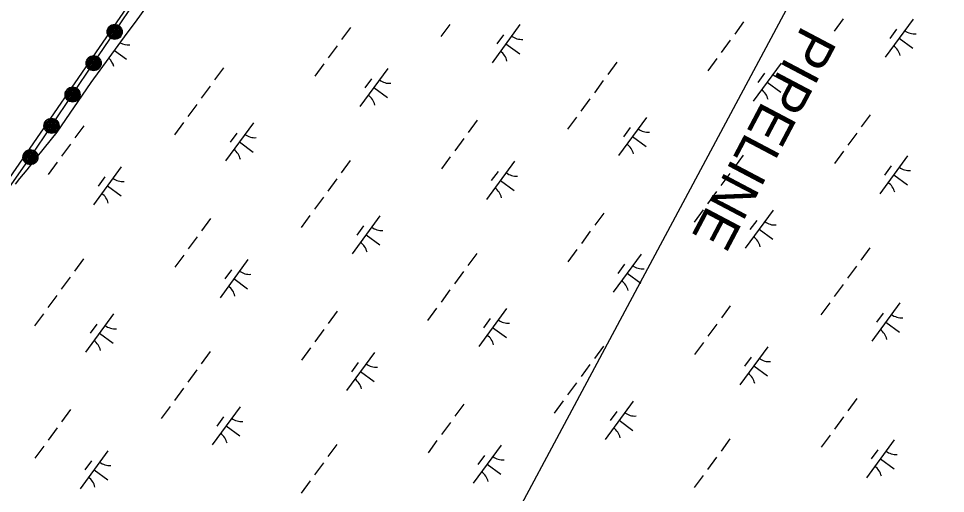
# Model space of a CAD drawing. Extents: x 3905714 to 3926767, y 183354 to 205755.
# Drawn here: x 3917054 to 3918037, y 190967 to 191470 of the extents above; entities that cross this region are included whole.
import ezdxf

# ---------------------------------------------------------------- set-up
doc = ezdxf.new("R2010")
doc.units = 0
for name, color, linetype in [('V-RIVR-EDGE', 7, 'Continuous'), ('V-RRAP-FSHR', 7, 'Continuous'), ('V-TOPO-SHOR', 7, 'Continuous'), ('V-UTIL-IDEN', 7, 'Continuous'), ('V-UTIL-LINE', 7, 'Continuous'), ('V-WETL-SWMP', 7, 'Continuous')]:
    doc.layers.add(name, color=color, linetype=linetype)

msp = doc.modelspace()

# ---------------------------------------------------------------- linework, layer by layer
at = {"layer": 'V-RIVR-EDGE'}
msp.add_lwpolyline([(3917620.57, 192168.81), (3917187.32, 191508.71), (3917014.39, 191257.68)], dxfattribs=at)
at = {"layer": 'V-RRAP-FSHR'}
for points in [[(3917043.93, 191290.26), (3917066.94, 191322.99), (3917089.31, 191356.14), (3917111.62, 191389.34), (3917133.93, 191422.55), (3917156.23, 191455.75), (3917178.54, 191488.95), (3917200.82, 191522.17), (3917223.43, 191555.43), (3917245.27, 191588.69), (3917267.49, 191621.95), (3917289.71, 191655.21), (3917311.94, 191688.47), (3917334.16, 191721.72), (3917356.37, 191754.99), (3917378.57, 191788.26), (3917400.78, 191821.54), (3917422.98, 191854.8), (3917444.62, 191888.45), (3917466.21, 191922.12), (3917487.8, 191955.79), (3917509.39, 191989.46)], [(3917154.18, 191448.72), (3917152.39, 191449.79), (3917150.04, 191452.07), (3917149.13, 191454.48), (3917149.34, 191457.68), (3917150.71, 191460.08), (3917153.18, 191462.3), (3917156.07, 191462.61), (3917158.34, 191462.63), (3917160.78, 191461.17), (3917162.4, 191459.24), (3917163.16, 191457), (3917163.26, 191454.79), (3917162.44, 191452.3), (3917160.02, 191449.81), (3917157.03, 191448.71), (3917154.62, 191448.81), (3917152.24, 191451.4), (3917150.45, 191453.77), (3917150.38, 191456.56), (3917151.59, 191459.56), (3917154.13, 191461.34), (3917157.13, 191461.62), (3917159.75, 191460.63), (3917161.71, 191458.26), (3917162.2, 191455.32), (3917160.93, 191452.12), (3917158.4, 191450.29), (3917155.66, 191449.77), (3917152.82, 191451.58), (3917151.54, 191454.02), (3917151.4, 191456.86), (3917152.71, 191459.29), (3917155.01, 191460.61), (3917157.77, 191460.62), (3917160.22, 191458.66), (3917161.17, 191455.98), (3917159.81, 191452.34), (3917157.38, 191450.87), (3917155.48, 191450.92), (3917153.27, 191453.04), (3917152.21, 191455.72), (3917152.94, 191458.05), (3917155.42, 191459.8), (3917157.76, 191459.46), (3917160, 191457.33), (3917159.96, 191454.92), (3917158.73, 191452.82), (3917156.88, 191451.7), (3917154.9, 191452.26), (3917153.85, 191453.95), (3917153.22, 191456.17), (3917154.28, 191457.96), (3917156.06, 191458.77), (3917158.14, 191458.08), (3917159.06, 191456.41), (3917158.9, 191454.65), (3917157.41, 191453), (3917156.08, 191452.87), (3917154.77, 191454.39), (3917154.34, 191456.26), (3917155.12, 191457.47), (3917156.68, 191457.58), (3917158.18, 191456.47), (3917157.97, 191454.85), (3917156.96, 191453.97), (3917155.54, 191454.79), (3917155.37, 191456.42), (3917156.52, 191456.67), (3917157.15, 191455.72), (3917156.86, 191454.92), (3917156.2, 191455.72)], [(3917131.87, 191415.52), (3917130.08, 191416.58), (3917127.74, 191418.86), (3917126.82, 191421.28), (3917127.03, 191424.48), (3917128.4, 191426.88), (3917130.87, 191429.09), (3917133.76, 191429.41), (3917136.04, 191429.43), (3917138.47, 191427.97), (3917140.1, 191426.03), (3917140.85, 191423.8), (3917140.95, 191421.58), (3917140.13, 191419.1), (3917137.71, 191416.6), (3917134.72, 191415.51), (3917132.32, 191415.61), (3917129.93, 191418.2), (3917128.14, 191420.57), (3917128.08, 191423.36), (3917129.28, 191426.36), (3917131.82, 191428.14), (3917134.82, 191428.41), (3917137.44, 191427.43), (3917139.4, 191425.05), (3917139.9, 191422.11), (3917138.63, 191418.91), (3917136.1, 191417.09), (3917133.35, 191416.57), (3917130.51, 191418.37), (3917129.23, 191420.82), (3917129.09, 191423.66), (3917130.41, 191426.09), (3917132.7, 191427.41), (3917135.46, 191427.42), (3917137.91, 191425.46), (3917138.86, 191422.77), (3917137.51, 191419.14), (3917135.08, 191417.67), (3917133.17, 191417.71), (3917130.96, 191419.83), (3917129.91, 191422.52), (3917130.63, 191424.85), (3917133.11, 191426.6), (3917135.46, 191426.26), (3917137.69, 191424.13), (3917137.66, 191421.72), (3917136.42, 191419.62), (3917134.58, 191418.5), (3917132.59, 191419.06), (3917131.54, 191420.75), (3917130.92, 191422.97), (3917131.98, 191424.76), (3917133.76, 191425.57), (3917135.83, 191424.88), (3917136.75, 191423.2), (3917136.59, 191421.44), (3917135.1, 191419.8), (3917133.78, 191419.67), (3917132.47, 191421.18), (3917132.04, 191423.06), (3917132.81, 191424.27), (3917134.37, 191424.38), (3917135.88, 191423.26), (3917135.67, 191421.64), (3917134.66, 191420.77), (3917133.23, 191421.59), (3917133.06, 191423.22), (3917134.21, 191423.46), (3917134.84, 191422.51), (3917134.56, 191421.72), (3917133.89, 191422.52)], [(3917109.56, 191382.32), (3917107.77, 191383.38), (3917105.43, 191385.66), (3917104.51, 191388.07), (3917104.73, 191391.28), (3917106.09, 191393.68), (3917108.57, 191395.89), (3917111.46, 191396.2), (3917113.73, 191396.23), (3917116.17, 191394.77), (3917117.79, 191392.83), (3917118.54, 191390.6), (3917118.64, 191388.38), (3917117.82, 191385.9), (3917115.4, 191383.4), (3917112.41, 191382.31), (3917110.01, 191382.41), (3917107.63, 191384.99), (3917105.83, 191387.36), (3917105.77, 191390.15), (3917106.97, 191393.15), (3917109.51, 191394.94), (3917112.52, 191395.21), (3917115.13, 191394.23), (3917117.1, 191391.85), (3917117.59, 191388.91), (3917116.32, 191385.71), (3917113.79, 191383.89), (3917111.04, 191383.37), (3917108.2, 191385.17), (3917106.92, 191387.62), (3917106.79, 191390.46), (3917108.1, 191392.89), (3917110.39, 191394.2), (3917113.15, 191394.22), (3917115.6, 191392.25), (3917116.55, 191389.57), (3917115.2, 191385.93), (3917112.77, 191384.47), (3917110.86, 191384.51), (3917108.66, 191386.63), (3917107.6, 191389.31), (3917108.32, 191391.65), (3917110.81, 191393.4), (3917113.15, 191393.06), (3917115.38, 191390.92), (3917115.35, 191388.51), (3917114.12, 191386.42), (3917112.27, 191385.3), (3917110.28, 191385.85), (3917109.23, 191387.55), (3917108.61, 191389.76), (3917109.67, 191391.55), (3917111.45, 191392.37), (3917113.52, 191391.68), (3917114.44, 191390), (3917114.28, 191388.24), (3917112.79, 191386.6), (3917111.47, 191386.47), (3917110.16, 191387.98), (3917109.73, 191389.86), (3917110.5, 191391.06), (3917112.06, 191391.18), (3917113.57, 191390.06), (3917113.36, 191388.44), (3917112.35, 191387.57), (3917110.93, 191388.38), (3917110.75, 191390.02), (3917111.91, 191390.26), (3917112.54, 191389.31), (3917112.25, 191388.52), (3917111.59, 191389.31)], [(3917087.26, 191349.12), (3917085.47, 191350.18), (3917083.12, 191352.46), (3917082.21, 191354.87), (3917082.42, 191358.08), (3917083.79, 191360.47), (3917086.26, 191362.69), (3917089.15, 191363), (3917091.42, 191363.03), (3917093.86, 191361.57), (3917095.48, 191359.63), (3917096.24, 191357.39), (3917096.34, 191355.18), (3917095.52, 191352.7), (3917093.1, 191350.2), (3917090.11, 191349.11), (3917087.7, 191349.2), (3917085.32, 191351.79), (3917083.53, 191354.16), (3917083.46, 191356.95), (3917084.67, 191359.95), (3917087.21, 191361.74), (3917090.21, 191362.01), (3917092.83, 191361.02), (3917094.79, 191358.65), (3917095.28, 191355.71), (3917094.01, 191352.51), (3917091.48, 191350.68), (3917088.74, 191350.17), (3917085.9, 191351.97), (3917084.62, 191354.42), (3917084.48, 191357.26), (3917085.79, 191359.69), (3917088.09, 191361), (3917090.85, 191361.02), (3917093.3, 191359.05), (3917094.25, 191356.37), (3917092.89, 191352.73), (3917090.46, 191351.26), (3917088.56, 191351.31), (3917086.35, 191353.43), (3917085.29, 191356.11), (3917086.02, 191358.44), (3917088.5, 191360.2), (3917090.84, 191359.86), (3917093.07, 191357.72), (3917093.04, 191355.31), (3917091.81, 191353.21), (3917089.96, 191352.09), (3917087.98, 191352.65), (3917086.93, 191354.34), (3917086.3, 191356.56), (3917087.36, 191358.35), (3917089.14, 191359.16), (3917091.22, 191358.47), (3917092.14, 191356.8), (3917091.98, 191355.04), (3917090.49, 191353.4), (3917089.16, 191353.26), (3917087.85, 191354.78), (3917087.42, 191356.65), (3917088.2, 191357.86), (3917089.76, 191357.98), (3917091.26, 191356.86), (3917091.05, 191355.24), (3917090.04, 191354.36), (3917088.62, 191355.18), (3917088.45, 191356.81), (3917089.6, 191357.06), (3917090.23, 191356.11), (3917089.94, 191355.31), (3917089.28, 191356.11)], [(3917064.73, 191316.01), (3917062.97, 191317.1), (3917060.67, 191319.43), (3917059.81, 191321.87), (3917060.09, 191325.07), (3917061.5, 191327.43), (3917064.02, 191329.6), (3917066.92, 191329.85), (3917069.19, 191329.82), (3917071.6, 191328.31), (3917073.18, 191326.34), (3917073.89, 191324.09), (3917073.94, 191321.87), (3917073.07, 191319.41), (3917070.59, 191316.96), (3917067.58, 191315.93), (3917065.18, 191316.08), (3917062.85, 191318.72), (3917061.11, 191321.13), (3917061.11, 191323.92), (3917062.37, 191326.89), (3917064.95, 191328.62), (3917067.96, 191328.83), (3917070.56, 191327.79), (3917072.47, 191325.38), (3917072.9, 191322.43), (3917071.56, 191319.25), (3917068.99, 191317.48), (3917066.24, 191317.02), (3917063.43, 191318.89), (3917062.21, 191321.36), (3917062.13, 191324.2), (3917063.5, 191326.6), (3917065.82, 191327.87), (3917068.58, 191327.83), (3917070.98, 191325.81), (3917071.88, 191323.11), (3917070.45, 191319.5), (3917067.98, 191318.08), (3917066.08, 191318.17), (3917063.92, 191320.34), (3917062.92, 191323.04), (3917063.69, 191325.36), (3917066.21, 191327.06), (3917068.55, 191326.67), (3917070.73, 191324.49), (3917070.65, 191322.08), (3917069.37, 191320.01), (3917067.5, 191318.92), (3917065.53, 191319.52), (3917064.52, 191321.24), (3917063.94, 191323.47), (3917065.04, 191325.24), (3917066.83, 191326.01), (3917068.89, 191325.28), (3917069.78, 191323.58), (3917069.58, 191321.83), (3917068.05, 191320.22), (3917066.73, 191320.11), (3917065.45, 191321.65), (3917065.06, 191323.54), (3917065.86, 191324.73), (3917067.42, 191324.81), (3917068.9, 191323.66), (3917068.66, 191322.05), (3917067.63, 191321.19), (3917066.22, 191322.04), (3917066.08, 191323.68), (3917067.24, 191323.9), (3917067.85, 191322.93), (3917067.55, 191322.14), (3917066.9, 191322.96)]]:
    msp.add_lwpolyline(points, dxfattribs=at)
for centre in [(3917156.23, 191455.75), (3917133.93, 191422.55), (3917111.62, 191389.35), (3917089.31, 191356.14), (3917066.94, 191322.99)]:
    msp.add_circle(centre, 8, dxfattribs=at)
at = {"layer": 'V-TOPO-SHOR'}
msp.add_lwpolyline([(3917051.15, 191294.52), (3917055.86, 191300.49), (3917063.34, 191309.67), (3917074.55, 191323.7), (3917095.19, 191349.54), (3917131.19, 191402.2), (3917169.41, 191454.44), (3917178.42, 191465.97), (3917191.16, 191483.89), (3917199.6, 191498.2), (3917229.36, 191546.82), (3917293.04, 191649.06), (3917339.54, 191727.55), (3917392.7, 191814.09), (3917467.19, 191926.89), (3917531.43, 192020.67)], dxfattribs=at)
at = {"layer": 'V-UTIL-LINE'}
msp.add_lwpolyline([(3922094.67, 198742.56), (3921080.02, 197477.61), (3915734.79, 187496.67)], dxfattribs=at)
at = {"layer": 'V-WETL-SWMP'}
for p, q in [((3917178.42, 191465.97), (3917191.16, 191483.89)), ((3917928.15, 191469.6), (3917918.7, 191456.69)), ((3917169.41, 191454.44), (3917178.42, 191465.97)), ((3917406.07, 191460.48), (3917396.61, 191447.58)), ((3917511.48, 191463.78), (3917502.02, 191450.87)), ((3917585.66, 191463.45), (3917556.11, 191423.11)), ((3917822.74, 191466.31), (3917813.29, 191453.4)), ((3918002.34, 191469.27), (3917972.79, 191428.94)), ((3917131.19, 191402.2), (3917169.41, 191454.44)), ((3917568.21, 191452.68), (3917561.12, 191443)), ((3917984.88, 191458.51), (3917977.79, 191448.83)), ((3917391.88, 191441.12), (3917382.43, 191428.22)), ((3917570.89, 191443.28), (3917585.41, 191432.64)), ((3917808.56, 191446.95), (3917799.1, 191434.04)), ((3917987.56, 191449.11), (3918002.08, 191438.47)), ((3917156.02, 191436.13), (3917168.74, 191426.82)), ((3917377.7, 191421.76), (3917368.24, 191408.86)), ((3917688.21, 191423.55), (3917678.76, 191410.64)), ((3917794.37, 191427.59), (3917784.92, 191414.68)), ((3917862.38, 191422.76), (3917832.83, 191382.42)), ((3917271.54, 191417.73), (3917262.08, 191404.82)), ((3917445.71, 191416.93), (3917416.16, 191376.6)), ((3917844.93, 191411.99), (3917837.84, 191402.31)), ((3917095.19, 191349.54), (3917131.19, 191402.2)), ((3917428.26, 191406.17), (3917421.16, 191396.49)), ((3917674.03, 191404.19), (3917664.57, 191391.28)), ((3917847.61, 191402.59), (3917862.13, 191391.95)), ((3917257.35, 191398.37), (3917247.9, 191385.46)), ((3917430.93, 191396.77), (3917445.45, 191386.13)), ((3917659.84, 191384.83), (3917650.39, 191371.92)), ((3917243.17, 191379.01), (3917233.71, 191366.1)), ((3917540.25, 191362.18), (3917530.79, 191349.27)), ((3917645.66, 191365.47), (3917636.2, 191352.56)), ((3917719.84, 191365.14), (3917690.29, 191324.81)), ((3917956.92, 191368), (3917947.46, 191355.1)), ((3917123.57, 191356.35), (3917114.12, 191343.45)), ((3917228.99, 191359.65), (3917219.53, 191346.74)), ((3917303.17, 191359.32), (3917273.62, 191318.98)), ((3917702.39, 191354.38), (3917695.3, 191344.7)), ((3917074.56, 191323.7), (3917095.19, 191349.54)), ((3917285.72, 191348.55), (3917278.62, 191338.87)), ((3917526.06, 191342.82), (3917516.61, 191329.91)), ((3917705.07, 191344.98), (3917719.59, 191334.34)), ((3917942.74, 191348.64), (3917933.28, 191335.74)), ((3917109.39, 191336.99), (3917099.93, 191324.09)), ((3917288.39, 191339.15), (3917302.91, 191328.51)), ((3917063.34, 191309.67), (3917074.56, 191323.7)), ((3917511.88, 191323.46), (3917502.42, 191310.55)), ((3917822.39, 191325.24), (3917812.93, 191312.34)), ((3917928.55, 191329.28), (3917919.1, 191316.38)), ((3917996.56, 191324.45), (3917967.01, 191284.12)), ((3917095.21, 191317.63), (3917085.75, 191304.73)), ((3917163.21, 191312.8), (3917133.66, 191272.47)), ((3917405.72, 191319.42), (3917396.26, 191306.51)), ((3917579.89, 191318.63), (3917550.34, 191278.29)), ((3917979.11, 191313.69), (3917972.02, 191304.01)), ((3917055.86, 191300.49), (3917063.34, 191309.67)), ((3917562.44, 191307.86), (3917555.34, 191298.18)), ((3917808.21, 191305.88), (3917798.75, 191292.98)), ((3917981.79, 191304.29), (3917996.31, 191293.65)), ((3917051.15, 191294.52), (3917055.86, 191300.49)), ((3917145.76, 191302.04), (3917138.67, 191292.36)), ((3917148.44, 191292.64), (3917162.96, 191282)), ((3917391.53, 191300.06), (3917382.08, 191287.15)), ((3917565.11, 191298.46), (3917579.63, 191287.82)), ((3917794.02, 191286.52), (3917784.57, 191273.62)), ((3917377.35, 191280.7), (3917367.89, 191267.79)), ((3917674.43, 191263.87), (3917664.97, 191250.97)), ((3917779.84, 191267.16), (3917770.38, 191254.26)), ((3917854.02, 191266.84), (3917824.47, 191226.5)), ((3917257.75, 191258.05), (3917248.3, 191245.14)), ((3917363.17, 191261.34), (3917353.71, 191248.43)), ((3917437.35, 191261.01), (3917407.8, 191220.68)), ((3917836.57, 191256.07), (3917829.48, 191246.39)), ((3917419.9, 191250.24), (3917412.8, 191240.56)), ((3917660.24, 191244.51), (3917650.79, 191231.61)), ((3917839.25, 191246.67), (3917853.77, 191236.03)), ((3917243.57, 191238.69), (3917234.11, 191225.78)), ((3917422.57, 191240.84), (3917437.09, 191230.21)), ((3917646.06, 191225.15), (3917636.6, 191212.25)), ((3917956.57, 191226.94), (3917947.11, 191214.03)), ((3917123.22, 191215.29), (3917113.77, 191202.38)), ((3917229.39, 191219.33), (3917219.93, 191206.42)), ((3917297.39, 191214.5), (3917267.84, 191174.16)), ((3917539.9, 191221.11), (3917530.44, 191208.21)), ((3917714.07, 191220.32), (3917684.52, 191179.99)), ((3917696.61, 191209.55), (3917689.52, 191199.87)), ((3917942.39, 191207.58), (3917932.93, 191194.67)), ((3917109.04, 191195.93), (3917099.58, 191183.02)), ((3917279.94, 191203.73), (3917272.85, 191194.05)), ((3917525.71, 191201.75), (3917516.26, 191188.85)), ((3917699.29, 191200.15), (3917713.81, 191189.52)), ((3917282.62, 191194.33), (3917297.14, 191183.69)), ((3917928.2, 191188.22), (3917918.75, 191175.31)), ((3917094.86, 191176.57), (3917085.4, 191163.66)), ((3917511.53, 191182.39), (3917502.07, 191169.49)), ((3917808.61, 191165.57), (3917799.15, 191152.66)), ((3917914.02, 191168.86), (3917904.56, 191155.95)), ((3917988.2, 191168.53), (3917958.65, 191128.2)), ((3917080.67, 191157.21), (3917071.22, 191144.3)), ((3917154.85, 191156.88), (3917125.3, 191116.55)), ((3917391.93, 191159.74), (3917382.48, 191146.84)), ((3917497.34, 191163.03), (3917487.89, 191150.13)), ((3917571.53, 191162.71), (3917541.98, 191122.37)), ((3917970.75, 191157.76), (3917963.66, 191148.08)), ((3917137.4, 191146.11), (3917130.31, 191136.43)), ((3917554.08, 191151.94), (3917546.98, 191142.26)), ((3917794.42, 191146.21), (3917784.97, 191133.3)), ((3917973.43, 191148.36), (3917987.95, 191137.73)), ((3917140.08, 191136.71), (3917154.6, 191126.08)), ((3917377.75, 191140.38), (3917368.29, 191127.47)), ((3917556.75, 191142.54), (3917571.27, 191131.9)), ((3917780.24, 191126.85), (3917770.78, 191113.94)), ((3917257.4, 191116.98), (3917247.95, 191104.08)), ((3917363.56, 191121.02), (3917354.11, 191108.11)), ((3917431.57, 191116.19), (3917402.02, 191075.86)), ((3917674.08, 191122.81), (3917664.62, 191109.9)), ((3917848.25, 191122.02), (3917818.7, 191081.68)), ((3917830.79, 191111.25), (3917823.7, 191101.57)), ((3917243.22, 191097.62), (3917233.76, 191084.72)), ((3917414.12, 191105.42), (3917407.03, 191095.74)), ((3917659.89, 191103.45), (3917650.44, 191090.54)), ((3917833.47, 191101.85), (3917847.99, 191091.21)), ((3917416.8, 191096.02), (3917431.32, 191085.39)), ((3917229.03, 191078.26), (3917219.58, 191065.36)), ((3917645.71, 191084.09), (3917636.25, 191071.18)), ((3917942.79, 191067.26), (3917933.33, 191054.35)), ((3917214.85, 191058.9), (3917205.39, 191046)), ((3917289.03, 191058.57), (3917259.48, 191018.24)), ((3917526.11, 191061.44), (3917516.66, 191048.53)), ((3917631.52, 191064.73), (3917622.07, 191051.82)), ((3917705.71, 191064.4), (3917676.16, 191024.07)), ((3917109.44, 191055.61), (3917099.98, 191042.7)), ((3917271.58, 191047.81), (3917264.49, 191038.13)), ((3917688.25, 191053.63), (3917681.16, 191043.95)), ((3917928.6, 191047.9), (3917919.15, 191034.99)), ((3917274.26, 191038.41), (3917288.78, 191027.77)), ((3917511.93, 191042.08), (3917502.47, 191029.17)), ((3917690.93, 191044.23), (3917705.45, 191033.59)), ((3917095.26, 191036.25), (3917085.8, 191023.34)), ((3917914.42, 191028.54), (3917904.96, 191015.63)), ((3917391.58, 191018.68), (3917382.13, 191005.77)), ((3917497.74, 191022.72), (3917488.29, 191009.81)), ((3917565.75, 191017.88), (3917536.2, 190977.55)), ((3917808.26, 191024.5), (3917798.8, 191011.6)), ((3917982.43, 191023.71), (3917952.88, 190983.38)), ((3917081.07, 191016.89), (3917071.61, 191003.98)), ((3917149.08, 191012.06), (3917119.53, 190971.73)), ((3917964.97, 191012.94), (3917957.88, 191003.26)), ((3917131.63, 191001.29), (3917124.53, 190991.61)), ((3917377.4, 190999.32), (3917367.94, 190986.41)), ((3917548.3, 191007.12), (3917541.21, 190997.44)), ((3917794.07, 191005.14), (3917784.62, 190992.24)), ((3917967.65, 191003.54), (3917982.17, 190992.9)), ((3917134.3, 190991.89), (3917148.82, 190981.25)), ((3917550.98, 190997.72), (3917565.5, 190987.08)), ((3917363.21, 190979.96), (3917353.76, 190967.05)), ((3917779.89, 190985.78), (3917770.43, 190972.88))]:
    msp.add_line(p, q, dxfattribs=at)
for centre, start, end in [((3917587.4, 191465.42), 232.99998, 274.54364), ((3918004.08, 191471.25), 232.99998, 274.54364), ((3917170.73, 191459.6), 240.2688, 274.54364), ((3917971.43, 191426.68), 12.99998, 54.54364), ((3917554.76, 191420.86), 12.99998, 54.54364), ((3917138.08, 191415.03), 12.99998, 47.23015), ((3917864.12, 191424.73), 232.99998, 274.54364), ((3917447.45, 191418.91), 232.99998, 274.54364), ((3917831.47, 191380.17), 12.99998, 54.54364), ((3917414.8, 191374.34), 12.99998, 54.54364), ((3917721.58, 191367.12), 232.99998, 274.54364), ((3917304.91, 191361.29), 232.99998, 274.54364), ((3917688.93, 191322.55), 12.99998, 54.54364), ((3917272.26, 191316.73), 12.99998, 54.54364), ((3917998.3, 191326.43), 232.99998, 274.54364), ((3917581.63, 191320.6), 232.99998, 274.54364), ((3917164.96, 191314.78), 232.99998, 274.54364), ((3917965.65, 191281.86), 12.99998, 54.54364), ((3917132.31, 191270.21), 12.99998, 54.54364), ((3917548.98, 191276.04), 12.99998, 54.54364), ((3917855.76, 191268.81), 232.99998, 274.54364), ((3917439.09, 191262.99), 232.99998, 274.54364), ((3917823.11, 191224.25), 12.99998, 54.54364), ((3917406.44, 191218.42), 12.99998, 54.54364), ((3917715.81, 191222.3), 232.99998, 274.54364), ((3917299.14, 191216.47), 232.99998, 274.54364), ((3917266.49, 191171.91), 12.99998, 54.54364), ((3917683.16, 191177.73), 12.99998, 54.54364), ((3917989.94, 191170.5), 232.99998, 274.54364), ((3917573.27, 191164.68), 232.99998, 274.54364), ((3917156.6, 191158.85), 232.99998, 274.54364), ((3917957.29, 191125.94), 12.99998, 54.54364), ((3917123.95, 191114.29), 12.99998, 54.54364), ((3917540.62, 191120.12), 12.99998, 54.54364), ((3917849.99, 191123.99), 232.99998, 274.54364), ((3917433.31, 191118.16), 232.99998, 274.54364), ((3917400.67, 191073.6), 12.99998, 54.54364), ((3917817.34, 191079.43), 12.99998, 54.54364), ((3917707.45, 191066.37), 232.99998, 274.54364), ((3917290.78, 191060.55), 232.99998, 274.54364), ((3917258.13, 191015.99), 12.99998, 54.54364), ((3917674.8, 191021.81), 12.99998, 54.54364), ((3917984.17, 191025.68), 232.99998, 274.54364), ((3917150.82, 191014.03), 232.99998, 274.54364), ((3917567.49, 191019.86), 232.99998, 274.54364), ((3917534.85, 190975.3), 12.99998, 54.54364), ((3917951.52, 190981.12), 12.99998, 54.54364), ((3917118.17, 190969.47), 12.99998, 54.54364)]:
    msp.add_arc(centre, 17.62, start, end, dxfattribs=at)

# ---------------------------------------------------------------- texts
at = {"layer": 'V-UTIL-IDEN'}
msp.add_text('PIPELINE', height=42, rotation=242.18275, dxfattribs=at).set_placement((3917885.17, 191463.84))

doc.saveas('drawing.dxf')
